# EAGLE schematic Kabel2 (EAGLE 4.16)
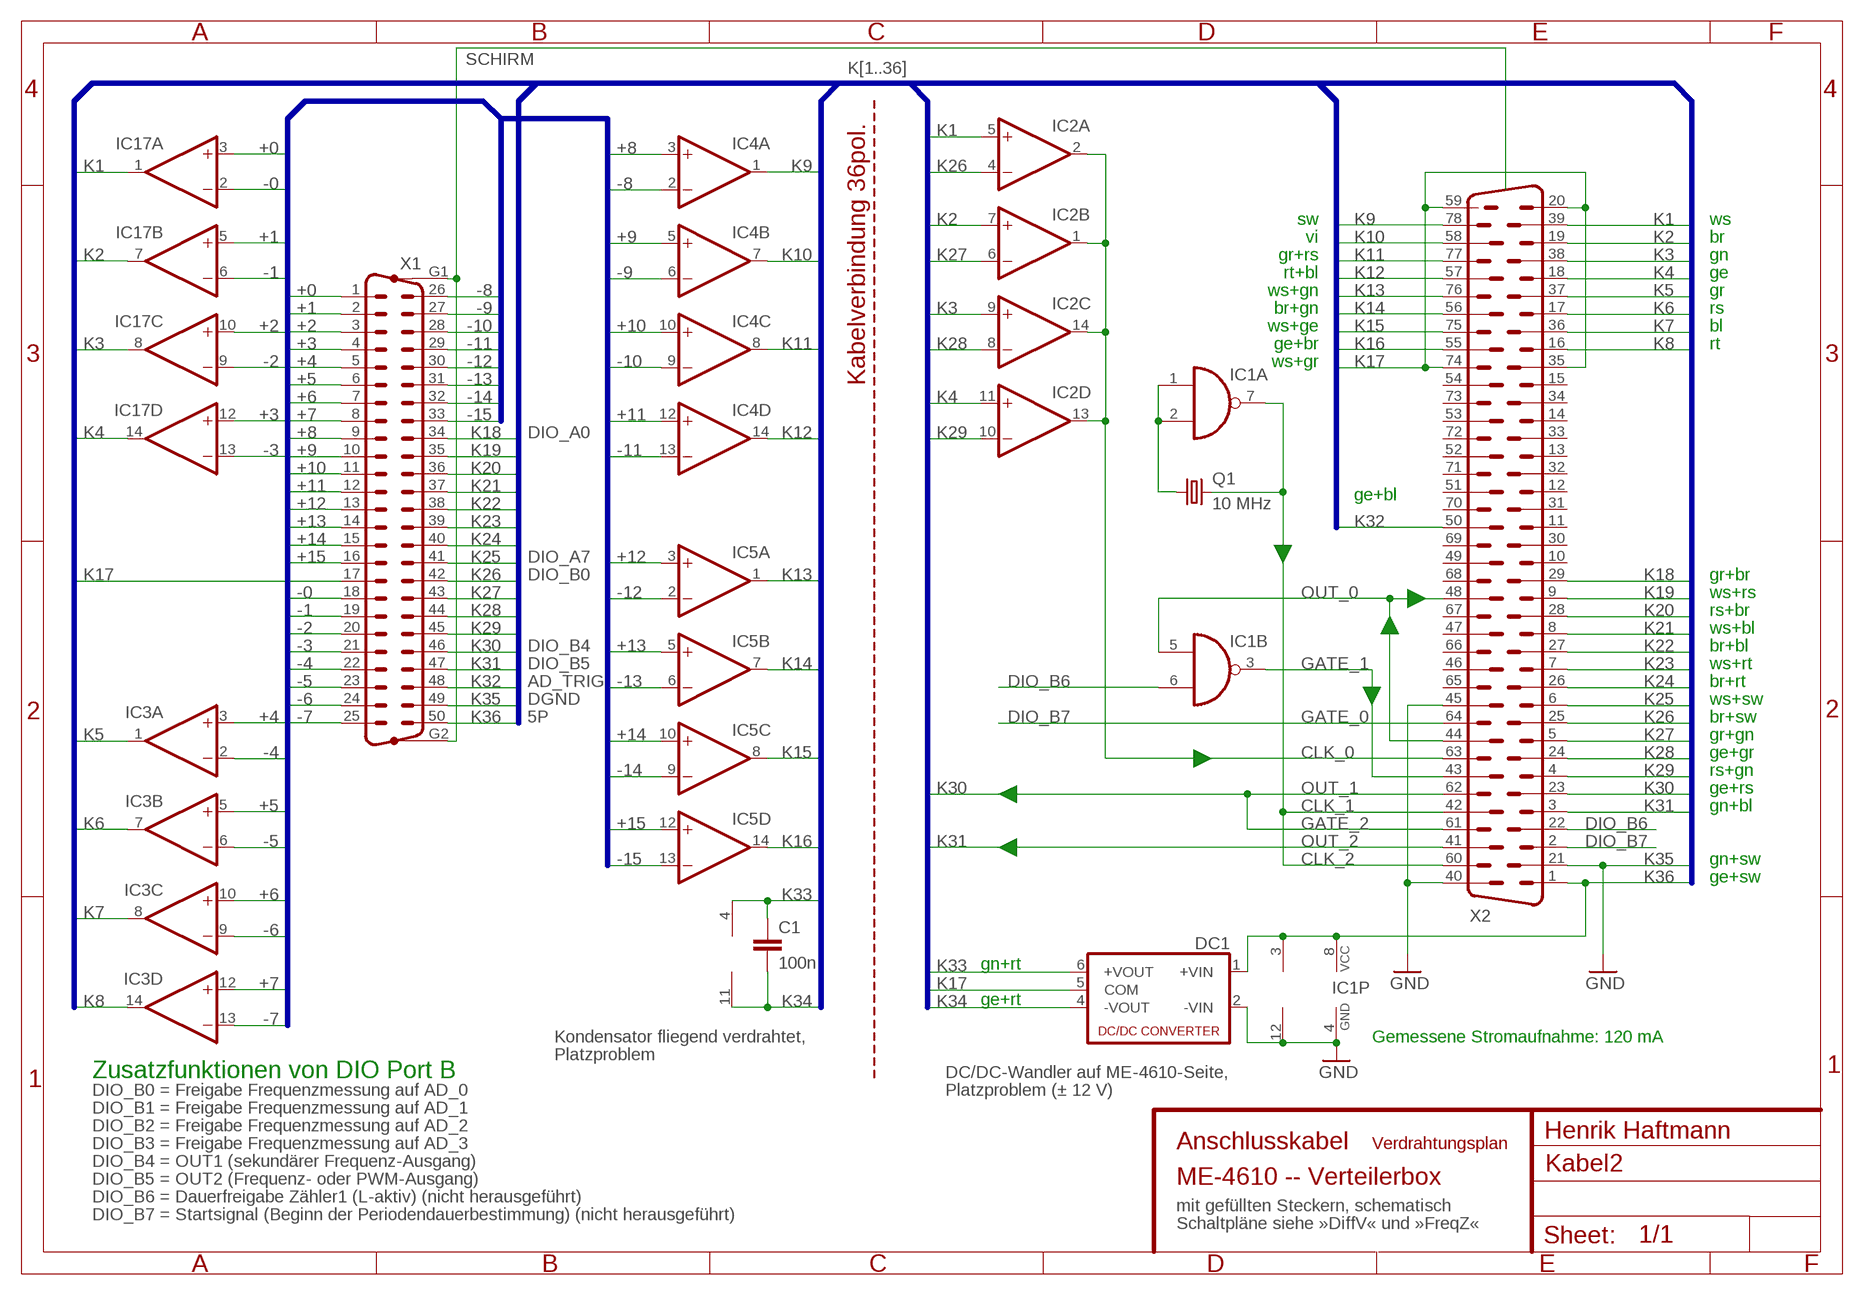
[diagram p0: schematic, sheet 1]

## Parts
C1  100n  C-EUC0603K  [C0603K]
DC1  NMA  [NMA]
IC1  74LVC2G00DCU  [DCU08]
IC2  LM339PW  [S14]
IC3  TL074D  [SO14]
IC4  TL074D  [SO14]
IC5  TL074D  [SO14]
IC17  TL074D  [SO14]
Q1  10 MHz  CRYSTALHC49U-V  [HC49U-V]
X1  M50VP  [M50VP]
X2  HM78V  [HDM78V]

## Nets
+0: IC17.3(A:+IN) X1.1
+1: IC17.5(B:+IN) X1.2
+2: IC17.10(C:+IN) X1.3
+3: IC17.12(D:+IN) X1.4
+4: IC3.3(A:+IN) X1.5
+5: IC3.5(B:+IN) X1.6
+6: IC3.10(C:+IN) X1.7
+7: IC3.12(D:+IN) X1.8
+8: IC4.3(A:+IN) X1.9
+9: IC4.5(B:+IN) X1.10
+10: IC4.10(C:+IN) X1.11
+11: IC4.12(D:+IN) X1.12
+12: IC5.3(A:+IN) X1.13
+13: IC5.5(B:+IN) X1.14
+14: IC5.10(C:+IN) X1.15
+15: IC5.12(D:+IN) X1.16
-0: IC17.2(A:-IN) X1.18
-1: IC17.6(B:-IN) X1.19
-2: IC17.9(C:-IN) X1.20
-3: IC17.13(D:-IN) X1.21
-4: IC3.2(A:-IN) X1.22
-5: IC3.6(B:-IN) X1.23
-6: IC3.9(C:-IN) X1.24
-7: IC3.13(D:-IN) X1.25
-8: IC4.2(A:-IN) X1.26
-9: IC4.6(B:-IN) X1.27
-10: IC4.9(C:-IN) X1.28
-11: IC4.13(D:-IN) X1.29
-12: IC5.2(A:-IN) X1.30
-13: IC5.6(B:-IN) X1.31
-14: IC5.9(C:-IN) X1.32
-15: IC5.13(D:-IN) X1.33
CLK_0: IC2.1(B:OUT) IC2.2(A:OUT) IC2.13(D:OUT) IC2.14(C:OUT) X2.63
DIO_B6: IC1.6(B:I1) X2.22
DIO_B7: X2.2 X2.64
GATE_1: IC1.3(B:O) X2.43
GND: DC1.2(-VIN) IC1.4(P:GND) IC2.12(P:GND)
K1: IC2.5(A:+IN) IC17.1(A:OUT) X2.39
K2: IC2.7(B:+IN) IC17.7(B:OUT) X2.19
K3: IC2.9(C:+IN) IC17.8(C:OUT) X2.38
K4: IC2.11(D:+IN) IC17.14(D:OUT) X2.18
K5: IC3.1(A:OUT) X2.37
K6: IC3.7(B:OUT) X2.17
K7: IC3.8(C:OUT) X2.36
K8: IC3.14(D:OUT) X2.16
K9: IC4.1(A:OUT) X2.78
K10: IC4.7(B:OUT) X2.58
K11: IC4.8(C:OUT) X2.77
K12: IC4.14(D:OUT) X2.57
K13: IC5.1(A:OUT) X2.76
K14: IC5.7(B:OUT) X2.56
K15: IC5.8(C:OUT) X2.75
K16: IC5.14(D:OUT) X2.55
K17: DC1.5(COM) X1.17 X2.20 X2.35 X2.59 X2.74
K18: X1.34 X2.29
K19: X1.35 X2.9
K20: X1.36 X2.28
K21: X1.37 X2.8
K22: X1.38 X2.27
K23: X1.39 X2.7
K24: X1.40 X2.26
K25: X1.41 X2.6
K26: IC2.4(A:-IN) X1.42 X2.25
K27: IC2.6(B:-IN) X1.43 X2.5
K28: IC2.8(C:-IN) X1.44 X2.24
K29: IC2.10(D:-IN) X1.45 X2.4
K30: X1.46 X2.23 X2.61 X2.62
K31: X1.47 X2.3 X2.41
K32: X1.48 X2.50
K33: C1.1 DC1.6(+VOUT) IC5.4(P:V+)
K34: C1.2 DC1.4(-VOUT) IC5.11(P:V-)
K35: X1.49 X2.21 X2.40 X2.45 ; supply symbol labelled GND
K36: DC1.1(+VIN) IC1.8(P:VCC) IC2.3(P:V+) X1.50 X2.1
N$1: IC1.1(A:I0) IC1.2(A:I1) Q1.1
N$2: IC1.7(A:O) Q1.2 X2.42 X2.60
OUT_0: IC1.5(B:I0) X2.44 X2.48
SCHIRM: X1.G1 X1.G2
Unconnected: X2.10 X2.11 X2.12 X2.13 X2.14 X2.15 X2.30 X2.31 X2.32 X2.33 X2.34 X2.46 X2.47 X2.49 X2.51 X2.52 X2.53 X2.54 X2.65 X2.66 X2.67 X2.68 X2.69 X2.70 X2.71 X2.72 X2.73

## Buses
K[1..36]
+[0..15],-[0..15]

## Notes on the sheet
- sw | ws
- vi | br
- gr+rs | gn
- rt+bl | ge
- ws+gn | gr
- br+gn | rs
- ws+ge | bl
- ge+br | rt
- ws+gr
- Kabelverbindung 36pol.
- DIO_A0
- ge+bl
- DIO_A7
- DIO_B0 | gr+br
- ws+rs
- rs+br
- ws+bl
- DIO_B4 | br+bl
- DIO_B5 | ws+rt
- AD_TRIG | br+rt
- DGND | ws+sw
- 5P | GATE_0 | br+sw
- gr+gn
- ge+gr
- rs+gn
- OUT_1 | ge+rs
- CLK_1 | gn+bl
- GATE_2
- OUT_2
- CLK_2 | gn+sw
- ge+sw
- gn+rt
- ge+rt
- Kondensator fliegend verdrahtet, | Gemessene Stromaufnahme: 120 mA
- Platzproblem
- Zusatzfunktionen von DIO Port B | DC/DC-Wandler auf ME-4610-Seite,
- DIO_B0 = Freigabe Frequenzmessung auf AD_0 | Platzproblem (± 12 V)
- DIO_B1 = Freigabe Frequenzmessung auf AD_1
- DIO_B2 = Freigabe Frequenzmessung auf AD_2
- Henrik Haftmann
- DIO_B3 = Freigabe Frequenzmessung auf AD_3 | Anschlusskabel | Verdrahtungsplan
- DIO_B4 = OUT1 (sekundärer Frequenz-Ausgang)
- DIO_B5 = OUT2 (Frequenz- oder PWM-Ausgang) | ME-4610 -- Verteilerbox
- DIO_B6 = Dauerfreigabe Zähler1 (L-aktiv) (nicht herausgeführt)
- mit gefüllten Steckern, schematisch
- DIO_B7 = Startsignal (Beginn der Periodendauerbestimmung) (nicht herausgeführt)
- Schaltpläne siehe »DiffV« und »FreqZ«

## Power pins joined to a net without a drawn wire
V+: IC3.4(P:V+) IC4.4(P:V+) IC17.4(P:V+)
V-: IC3.11(P:V-) IC4.11(P:V-) IC17.11(P:V-)

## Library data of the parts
C1 = rcl:C-EU: CAPACITOR, European symbol
DC1 = dc-dc-converter:NMA: DC-DC CONVERTER
IC1 = DiffV:74*2G00: Dual 2-input NAND gate AUC = 3,3 V maximal!
IC2 = DiffV:LM339: Low Power Low Offset Voltage Quad Comparators with open collector; LM139/LM239/LM339/LM2901/LM3302
IC3-IC5 IC17 = linear:TL074: OP AMP
Q1 = crystal:CRYSTAL: CRYSTAL
X1 = con-subd:M50VP: SUB-D
X2 = con-subd:HM78V: SUB-D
